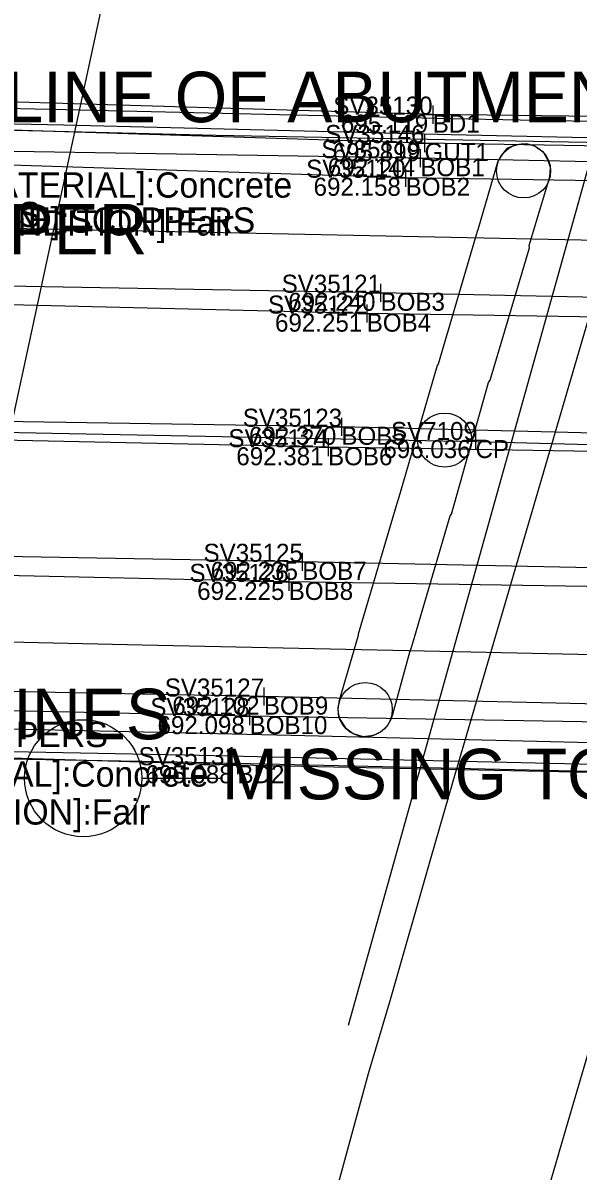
# Model space of a CAD drawing. Extents: x 1659932 to 1663108, y 619867 to 620611.
# Drawn here: x 1661268.5 to 1661299.3, y 620192.5 to 620256.1 of the extents above; entities that cross this region are included whole.
import ezdxf

# ---------------------------------------------------------------- set-up
doc = ezdxf.new("R2010")
doc.units = 0
for name, color, linetype in [('BR_X_Rail_Object', 7, 'Continuous'), ('BR_X_SV_Bottom_of_Beam', 7, 'Continuous'), ('BR_X_SV_Bottom_of_Beam_Text', 7, 'Continuous'), ('BR_X_SV_Deck_Top', 7, 'Continuous'), ('BR_X_SV_Deck_Top_Text', 7, 'Continuous'), ('BR_X_SV_Pier_Cap_Top', 7, 'Continuous'), ('PM_X_CL_Double_Solid', 7, 'Continuous'), ('PM_X_Edge_Line', 7, 'Continuous'), ('PV_X_Curb', 7, 'Continuous'), ('PV_X_EOP', 7, 'Continuous'), ('RD_X_GR_Rt', 7, 'Continuous'), ('RD_X_Text', 7, 'Continuous'), ('SC_Scratch6', 7, 'Continuous'), ('SV_X_Break_Lines', 7, 'Continuous'), ('SV_X_Shot_Marker', 7, 'Continuous'), ('SV_X_Text', 7, 'Continuous'), ('SV_X_Text_Comment', 7, 'Continuous'), ('SV_X_Text_Elevation', 7, 'Continuous'), ('SV_X_Text_Name', 7, 'Continuous'), ('SV_X_Toe_of_Slope', 7, 'Continuous')]:
    doc.layers.add(name, color=color, linetype=linetype)

msp = doc.modelspace()

# ---------------------------------------------------------------- linework, layer by layer
at = {"layer": 'BR_X_Rail_Object'}
for points in [[(1661312.412, 620250.402), (1661292.245, 620250.78), (1661270.899, 620251.272), (1661247.366, 620251.791), (1661237.299, 620252), (1661237.309, 620251.128), (1661247.431, 620250.924), (1661270.809, 620250.444), (1661292.272, 620249.911), (1661312.353, 620249.471)], [(1661300.196, 620215.004), (1661277.496, 620215.529), (1661254.423, 620215.977), (1661244.278, 620216.225), (1661227.533, 620216.591), (1661227.344, 620215.991), (1661244.282, 620215.701), (1661254.224, 620215.561), (1661277.086, 620215.156), (1661299.829, 620214.642)]]:
    msp.add_lwpolyline(points, dxfattribs=at)
at = {"layer": 'BR_X_SV_Bottom_of_Beam'}
for points in [[(1661523.404, 620243.849), (1661497.415, 620244.383), (1661471.694, 620244.95), (1661445.773, 620245.45), (1661419.903, 620245.974), (1661394.009, 620246.51), (1661368.147, 620247.032), (1661342.287, 620247.488), (1661316.311, 620248.045), (1661290.557, 620248.602), (1661264.648, 620249.031), (1661238.6, 620249.579)], [(1661517.582, 620243.008), (1661496.897, 620243.44), (1661470.919, 620243.838), (1661445.09, 620244.441), (1661419.147, 620244.946), (1661393.26, 620245.417), (1661367.358, 620245.921), (1661341.629, 620246.518), (1661315.646, 620247.115), (1661289.746, 620247.518), (1661264.383, 620248.322), (1661238.204, 620248.614)], [(1661521.265, 620236.365), (1661495.332, 620236.959), (1661469.491, 620237.512), (1661443.572, 620237.996), (1661417.708, 620238.508), (1661391.884, 620239.08), (1661365.994, 620239.561), (1661340.119, 620240.034), (1661314.197, 620240.589), (1661288.354, 620241.145), (1661262.476, 620241.611), (1661236.623, 620242.15)], [(1661520.605, 620235.452), (1661494.63, 620235.975), (1661468.71, 620236.383), (1661442.944, 620236.996), (1661417.103, 620237.514), (1661391.103, 620237.982), (1661365.202, 620238.448), (1661339.374, 620239.07), (1661313.502, 620239.591), (1661287.59, 620239.99), (1661261.723, 620240.632), (1661235.908, 620241.144)], [(1661519.081, 620228.953), (1661493.234, 620229.438), (1661467.368, 620230.031), (1661441.422, 620230.57), (1661415.6, 620231.071), (1661389.731, 620231.651), (1661363.823, 620232.132), (1661337.817, 620232.613), (1661311.988, 620233.076), (1661286.183, 620233.721), (1661260.328, 620234.129), (1661234.382, 620234.656)], [(1661518.51, 620227.977), (1661492.527, 620228.475), (1661466.56, 620228.954), (1661440.742, 620229.56), (1661414.823, 620230.069), (1661388.938, 620230.522), (1661363.07, 620231.021), (1661337.298, 620231.612), (1661311.527, 620232.162), (1661285.446, 620232.587), (1661259.588, 620233.138), (1661233.669, 620233.674)], [(1661516.938, 620221.488), (1661491.079, 620222.019), (1661465.187, 620222.58), (1661439.251, 620223.092), (1661413.441, 620223.61), (1661387.584, 620224.174), (1661361.703, 620224.657), (1661335.742, 620225.126), (1661309.876, 620225.693), (1661284.015, 620226.238), (1661258.155, 620226.696), (1661232.1, 620227.235)], [(1661516.255, 620220.542), (1661490.624, 620220.907), (1661464.53, 620221.454), (1661438.64, 620222.101), (1661412.707, 620222.613), (1661386.76, 620223.066), (1661360.949, 620223.557), (1661335.05, 620224.176), (1661309.206, 620224.717), (1661283.267, 620225.126), (1661257.537, 620225.694), (1661231.605, 620226.262)], [(1661514.756, 620214.059), (1661488.914, 620214.555), (1661463.017, 620215.148), (1661437.126, 620215.616), (1661411.256, 620216.167), (1661385.428, 620216.691), (1661359.541, 620217.184), (1661333.602, 620217.682), (1661307.754, 620218.183), (1661281.891, 620218.773), (1661255.858, 620219.275), (1661229.67, 620219.799)], [(1661514.073, 620213.08), (1661488.21, 620213.597), (1661462.263, 620214.044), (1661436.515, 620214.643), (1661410.516, 620215.165), (1661384.602, 620215.601), (1661358.815, 620216.084), (1661332.968, 620216.701), (1661307.113, 620217.251), (1661281.101, 620217.691), (1661255.319, 620218.266), (1661229.464, 620218.851)]]:
    msp.add_lwpolyline(points, dxfattribs=at)
at = {"layer": 'BR_X_SV_Deck_Top'}
for points in [[(1661524.154, 620246.519), (1661498.291, 620247.067), (1661472.426, 620247.598), (1661446.524, 620248.074), (1661420.55, 620248.604), (1661394.772, 620249.021), (1661368.927, 620249.743), (1661342.743, 620250.117), (1661316.866, 620250.706), (1661291.246, 620251.013), (1661265.132, 620251.796)], [(1661513.529, 620210.295), (1661487.664, 620211.099), (1661461.66, 620211.354), (1661435.632, 620211.885), (1661409.962, 620212.424), (1661383.838, 620212.928), (1661332.298, 620213.947), (1661306.248, 620214.439), (1661280.429, 620214.969), (1661254.732, 620215.771)]]:
    msp.add_lwpolyline(points, dxfattribs=at)
at = {"layer": 'BR_X_SV_Pier_Cap_Top'}
msp.add_lwpolyline([(1661294.86, 620248.433), (1661293.746, 620244.636), (1661293.71, 620244.541), (1661291.55, 620237.191), (1661291.493, 620237.119), (1661289.323, 620229.687), (1661289.31, 620229.645), (1661287.109, 620222.229), (1661287.121, 620222.152), (1661286.067, 620218.557), (1661285.985, 620218.141), (1661286.001, 620217.835), (1661286.033, 620217.639), (1661286.408, 620217.043), (1661286.832, 620216.73), (1661287.375, 620216.563), (1661287.991, 620216.626), (1661288.395, 620216.83), (1661288.729, 620217.132), (1661288.945, 620217.518), (1661289.035, 620217.791), (1661289.997, 620221.309), (1661290.065, 620221.483), (1661292.215, 620228.793), (1661292.285, 620228.873), (1661294.337, 620236.172), (1661294.429, 620236.307), (1661296.606, 620243.641), (1661296.595, 620243.767), (1661297.736, 620247.561), (1661297.776, 620248.08), (1661297.647, 620248.47), (1661297.373, 620248.938), (1661297.19, 620249.039), (1661296.864, 620249.283), (1661296.431, 620249.395), (1661296.14, 620249.386), (1661295.799, 620249.325), (1661295.343, 620249.144), (1661295.067, 620248.782), (1661294.961, 620248.604), (1661294.86, 620248.433)], dxfattribs=at)
at = {"layer": 'PM_X_CL_Double_Solid'}
msp.add_lwpolyline([(1661546.991, 620228.003), (1661534.02, 620228.314), (1661515.703, 620228.672), (1661490.63, 620229.199), (1661465.719, 620229.574), (1661443.889, 620229.917), (1661424.27, 620230.219), (1661405.796, 620230.53), (1661384.669, 620230.881), (1661362.569, 620231.272), (1661341.508, 620231.739), (1661317.992, 620232.235), (1661293.686, 620232.891), (1661270.168, 620233.351), (1661246.396, 620233.829), (1661221.676, 620234.257), (1661205.714, 620234.618)], dxfattribs=at)
at = {"layer": 'PM_X_Edge_Line'}
for points in [[(1661550.118, 620239.201), (1661538.667, 620239.519), (1661512.091, 620240.179), (1661488.878, 620240.663), (1661465.84, 620241.071), (1661441.891, 620241.445), (1661414.819, 620241.887), (1661388.375, 620242.338), (1661361.281, 620242.854), (1661333.713, 620243.371), (1661302.167, 620244.004), (1661273.353, 620244.591), (1661246.421, 620245.132), (1661216.402, 620245.664), (1661208.501, 620245.807)], [(1661202.201, 620223.591), (1661213.111, 620223.268), (1661228.394, 620222.766), (1661259.553, 620221.998), (1661275.152, 620221.639), (1661292.516, 620221.273), (1661314.563, 620220.783), (1661337.968, 620220.356), (1661364.828, 620219.904), (1661379.245, 620219.635), (1661405.952, 620219.205), (1661427.476, 620218.875), (1661447.989, 620218.475), (1661471.403, 620218.024), (1661496.022, 620217.585), (1661519.238, 620217.199), (1661540.284, 620216.766), (1661543.975, 620216.723)], [(1661205.757, 619869.483), (1661211.13, 619888.813), (1661217.408, 619910.983), (1661224.336, 619935.2), (1661231.75, 619961.45), (1661235.507, 619974.894), (1661240.671, 619993.145), (1661247.926, 620018.654), (1661255.82, 620046.312), (1661265.009, 620078.439), (1661274.649, 620112.11), (1661283.801, 620143.927), (1661298.651, 620194.915), (1661304.258, 620213.966)]]:
    msp.add_lwpolyline(points, dxfattribs=at)
at = {"layer": 'PV_X_Curb'}
msp.add_lwpolyline([(1661523.342, 620245.121), (1661471.566, 620246.113), (1661445.996, 620246.597), (1661316.22, 620249.01), (1661290.79, 620249.439), (1661264.952, 620250.247), (1661238.714, 620250.79)], dxfattribs=at)
at = {"layer": 'PV_X_EOP'}
msp.add_line((1661292.372, 620214.085), (1661303.392, 620251.732), dxfattribs=at)
msp.add_lwpolyline([(1661194.327, 619870.94), (1661199.117, 619888.311), (1661202.827, 619901.545), (1661213.74, 619940.002), (1661227.283, 619987.12), (1661233.26, 620009.055), (1661239.435, 620029.761), (1661246.226, 620053.023), (1661255.141, 620084.211), (1661258.721, 620096.738), (1661262.228, 620108.924), (1661266.246, 620123.087), (1661272.333, 620144.562), (1661276.821, 620159.807), (1661281.773, 620177.171), (1661285.401, 620189.508), (1661287.684, 620197.891), (1661288.911, 620201.994), (1661291.147, 620209.792), (1661292.372, 620214.085)], dxfattribs=at)
at = {"layer": 'RD_X_GR_Rt'}
msp.add_line((1661307.299, 620274.779), (1661286.563, 620200.556), dxfattribs=at)
at = {"layer": 'SC_Scratch6'}
msp.add_line((1661275.127, 620214.246), (1661279.557, 620214.246), dxfattribs=at)
msp.add_circle((1661271.883, 620214.246), 3.245, dxfattribs=at)
at = {"layer": 'SV_X_Break_Lines'}
for points in [[(1661238.016, 620250.735), (1661242.286, 620250.672), (1661247.517, 620250.551), (1661257.182, 620250.394), (1661265.859, 620250.202), (1661279.254, 620249.879), (1661300.715, 620249.466), (1661326.88, 620248.933), (1661355.543, 620248.374), (1661388.796, 620247.704), (1661434.33, 620246.78), (1661467.071, 620246.096), (1661484, 620245.717), (1661498.395, 620245.527), (1661509.52, 620245.356), (1661518.819, 620245.069), (1661524.432, 620245.01)], [(1661228.67, 620217.714), (1661237.329, 620217.546), (1661248.531, 620217.329), (1661262.126, 620217.116), (1661283.4, 620216.641), (1661303.8, 620216.137), (1661335.243, 620215.455), (1661384.24, 620214.497), (1661403.674, 620214.086), (1661434.655, 620213.563), (1661466.755, 620212.973), (1661495.661, 620212.446), (1661513.396, 620212.012)]]:
    msp.add_lwpolyline(points, dxfattribs=at)
for centre in [(1661296.278, 620247.898), (1661291.908, 620232.981), (1661287.506, 620218.05)]:
    msp.add_circle(centre, 1.5, dxfattribs=at)
at = {"layer": 'SV_X_Shot_Marker'}
for p, q in [((1661291.246, 620251.513), (1661291.246, 620250.513)), ((1661290.746, 620251.013), (1661291.746, 620251.013)), ((1661291.246, 620251.013), (1661291.246, 620251.013)), ((1661290.79, 620249.939), (1661290.79, 620248.939)), ((1661290.29, 620249.439), (1661291.29, 620249.439)), ((1661290.557, 620249.102), (1661290.557, 620248.102)), ((1661290.79, 620249.439), (1661290.79, 620249.439)), ((1661290.057, 620248.602), (1661291.057, 620248.602)), ((1661290.557, 620248.602), (1661290.557, 620248.602)), ((1661289.746, 620248.018), (1661289.746, 620247.018)), ((1661289.246, 620247.518), (1661290.246, 620247.518)), ((1661289.746, 620247.518), (1661289.746, 620247.518)), ((1661288.354, 620241.645), (1661288.354, 620240.645)), ((1661287.854, 620241.145), (1661288.854, 620241.145)), ((1661288.354, 620241.145), (1661288.354, 620241.145)), ((1661287.09, 620239.99), (1661288.09, 620239.99)), ((1661287.59, 620240.49), (1661287.59, 620239.49)), ((1661287.59, 620239.99), (1661287.59, 620239.99)), ((1661285.683, 620233.721), (1661286.683, 620233.721)), ((1661286.183, 620234.221), (1661286.183, 620233.221)), ((1661286.183, 620233.721), (1661286.183, 620233.721)), ((1661285.446, 620233.087), (1661285.446, 620232.087)), ((1661293.615, 620233.486), (1661293.615, 620232.486)), ((1661284.946, 620232.587), (1661285.946, 620232.587)), ((1661285.446, 620232.587), (1661285.446, 620232.587)), ((1661293.115, 620232.986), (1661294.115, 620232.986)), ((1661293.615, 620232.986), (1661293.615, 620232.986)), ((1661284.015, 620226.738), (1661284.015, 620225.738)), ((1661283.515, 620226.238), (1661284.515, 620226.238)), ((1661284.015, 620226.238), (1661284.015, 620226.238)), ((1661283.267, 620225.626), (1661283.267, 620224.626)), ((1661282.767, 620225.126), (1661283.767, 620225.126)), ((1661283.267, 620225.126), (1661283.267, 620225.126)), ((1661281.891, 620219.273), (1661281.891, 620218.273)), ((1661281.391, 620218.773), (1661282.391, 620218.773)), ((1661281.891, 620218.773), (1661281.891, 620218.773)), ((1661281.101, 620218.191), (1661281.101, 620217.191)), ((1661280.601, 620217.691), (1661281.601, 620217.691)), ((1661281.101, 620217.691), (1661281.101, 620217.691)), ((1661280.429, 620215.469), (1661280.429, 620214.469)), ((1661279.929, 620214.969), (1661280.929, 620214.969)), ((1661280.429, 620214.969), (1661280.429, 620214.969))]:
    msp.add_line(p, q, dxfattribs=at)
at = {"layer": 'SV_X_Toe_of_Slope'}
msp.add_lwpolyline([(1661237.229, 620169.637), (1661259.655, 620195.623), (1661277.405, 620277.795), (1661264.309, 620300.267)], dxfattribs=at)

# ---------------------------------------------------------------- texts
at = {"layer": 'BR_X_SV_Bottom_of_Beam_Text'}
for s, p in [('SV35119', (1661285.077, 620248.602)), ('SV35120', (1661284.236, 620247.518)), ('692.144', (1661285.435, 620247.602)), ('BOB1', (1661290.557, 620247.602)), ('692.158', (1661284.646, 620246.518)), ('BOB2', (1661289.746, 620246.518)), ('SV35121', (1661282.876, 620241.145)), ('SV35122', (1661282.121, 620239.99)), ('692.240', (1661283.24, 620240.145)), ('BOB3', (1661288.354, 620240.145)), ('692.251', (1661282.508, 620238.99)), ('BOB4', (1661287.59, 620238.99)), ('SV35123', (1661280.723, 620233.721)), ('692.370', (1661281.069, 620232.721)), ('BOB5', (1661286.183, 620232.721)), ('SV35124', (1661279.928, 620232.587)), ('692.381', (1661280.364, 620231.587)), ('BOB6', (1661285.446, 620231.587)), ('SV35125', (1661278.548, 620226.238)), ('SV35126', (1661277.767, 620225.126)), ('692.235', (1661278.945, 620225.238)), ('BOB7', (1661284.015, 620225.238)), ('692.225', (1661278.197, 620224.126)), ('BOB8', (1661283.267, 620224.126)), ('SV35127', (1661276.399, 620218.773)), ('SV35128', (1661275.604, 620217.691)), ('692.102', (1661276.818, 620217.773)), ('BOB9', (1661281.891, 620217.773)), ('692.098', (1661276.001, 620216.691)), ('BOB10', (1661281.101, 620216.691))]:
    msp.add_text(s, height=1, dxfattribs=at).set_placement(p)
at = {"layer": 'BR_X_SV_Deck_Top_Text'}
for s, p in [('SV35130', (1661285.736, 620251.013)), ('695.119', (1661286.162, 620250.013)), ('BD1', (1661291.246, 620250.013)), ('SV35131', (1661274.951, 620214.969)), ('695.088', (1661275.329, 620213.969)), ('BD2', (1661280.429, 620213.969))]:
    msp.add_text(s, height=1, dxfattribs=at).set_placement(p)
at = {"layer": 'RD_X_Text'}
msp.add_text('SCUPPER', height=2.8, dxfattribs=at).set_placement((1661257.344, 620243.265))
at = {"layer": 'SC_Scratch6'}
for s, p in [('MISSING OUTLINE OF ABUTMENT', (1661242.831, 620250.594)), ('MISSING BREAK LINES', (1661235.334, 620216.406)), ('MISSING TOE OF BARRIER', (1661279.557, 620213.079))]:
    msp.add_text(s, height=2.79999, dxfattribs=at).set_placement(p)
at = {"layer": 'SV_X_Text'}
for s, p in [('[MATERIAL]:Concrete', (1661264.939, 620246.415)), ('[NOTE]:SCUPPERS', (1661252.475, 620244.782)), ('[NOTE]:SCUPPERS', (1661264.352, 620244.471)), ('[CONDITION]:Fair', (1661264.939, 620244.315)), ('[NOTE]:SCUPPERS', (1661256.189, 620215.973)), ('[MATERIAL]:Concrete', (1661260.298, 620213.781)), ('[CONDITION]:Fair', (1661260.298, 620211.681))]:
    msp.add_text(s, height=1.4, dxfattribs=at).set_placement(p)
at = {"layer": 'SV_X_Text_Comment'}
for s, p in [('GUT1', (1661290.79, 620248.439)), ('CP', (1661293.615, 620231.986))]:
    msp.add_text(s, height=1, dxfattribs=at).set_placement(p)
at = {"layer": 'SV_X_Text_Elevation'}
for s, p in [('695.899', (1661285.706, 620248.439)), ('696.036', (1661288.511, 620231.986))]:
    msp.add_text(s, height=1, dxfattribs=at).set_placement(p)
at = {"layer": 'SV_X_Text_Name'}
for s, p in [('SV35146', (1661285.29, 620249.439)), ('SV7109', (1661288.933, 620232.986))]:
    msp.add_text(s, height=1, dxfattribs=at).set_placement(p)

doc.saveas('drawing.dxf')
